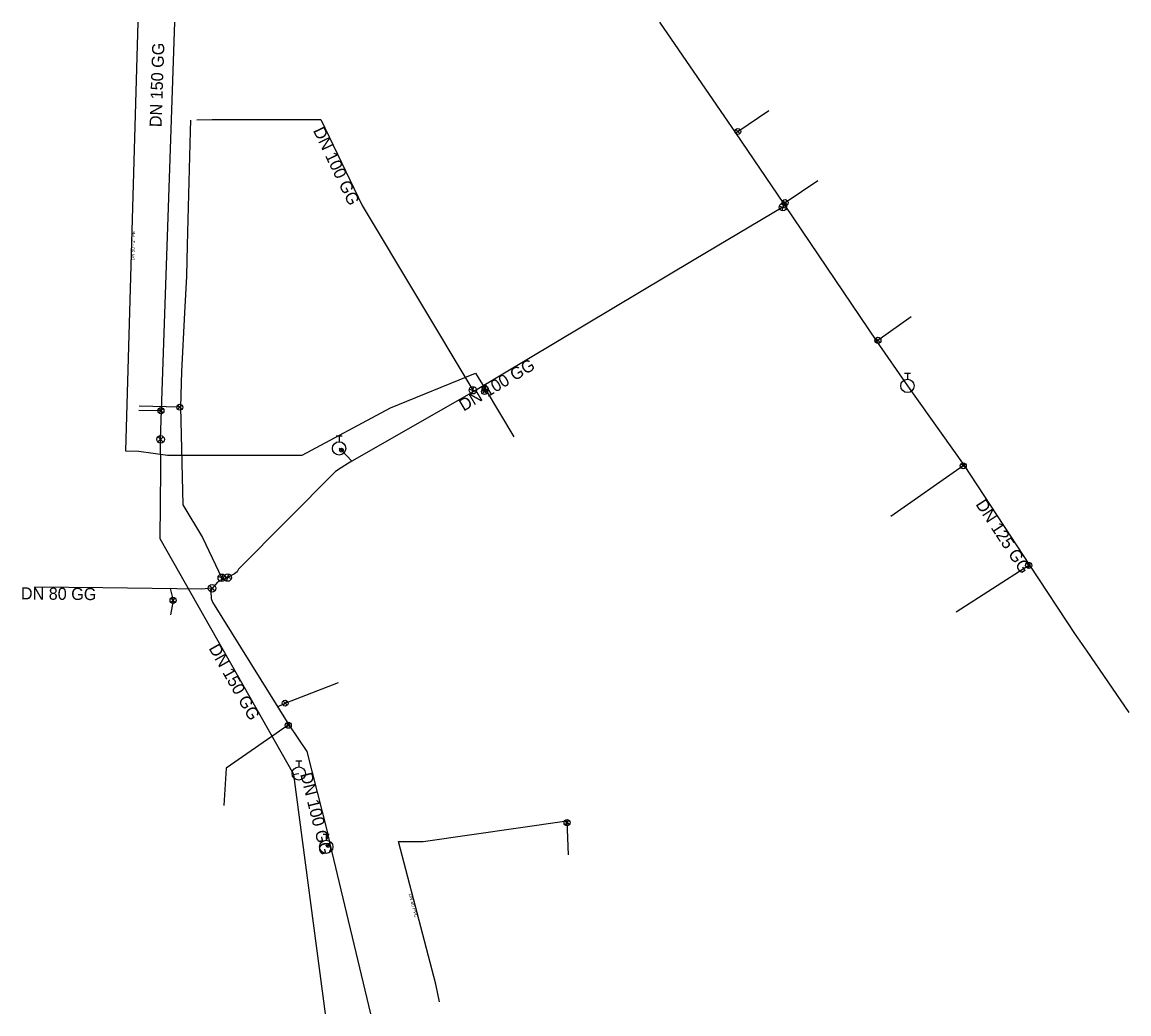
# Model space of a CAD drawing. Extents: x -464788 to -464641, y -1094693 to -1094561.
import ezdxf

# ---------------------------------------------------------------- set-up
doc = ezdxf.new("R2010")
doc.units = 0
for name, color, linetype in [('_hydrantova_odbocka_', 7, 'Continuous'), ('_pripojka_prevzato_z_dokumentace_', 7, 'Continuous'), ('_pripojka_priblizne_', 7, 'Continuous'), ('_voda_smvak_prevzato_z_dokumentace_', 7, 'Continuous'), ('_voda_smvak_priblizne_', 7, 'Continuous'), ('Default', 7, 'Continuous'), ('MoLevel 2', 7, 'Continuous'), ('MoLevel 27', 7, 'Continuous'), ('MoLevel 28', 7, 'Continuous'), ('MoLevel 32', 7, 'Continuous'), ('MoLevel 46', 7, 'Continuous'), ('MoLevel 53', 7, 'Continuous'), ('MoLevel 55', 7, 'Continuous')]:
    doc.layers.add(name, color=color, linetype=linetype)

# ---------------------------------------------------------------- blocks, each defined once
blk = doc.blocks.new('_uzaver_')
at = {"layer": 'Default'}
for p, q in [((-0.000035, -0.000035), (0.000035, 0.000035)), ((0.000035, -0.000035), (-0.000035, 0.000035))]:
    blk.add_line(p, q, dxfattribs=at)
for radius in [0.00005, 0.0000025]:
    blk.add_circle((0, 0), radius, dxfattribs=at)
blk = doc.blocks.new('_uzaver_pripojka_')
at = {"layer": 'Default'}
for p, q in [((-0.000035, -0.000035), (0.000035, 0.000035)), ((0.000035, -0.000035), (-0.000035, 0.000035))]:
    blk.add_line(p, q, dxfattribs=at)
for radius in [0.00005, 0.0000025]:
    blk.add_circle((0, 0), radius, dxfattribs=at)
blk = doc.blocks.new('_hydrant_voda_')
at = {"layer": 'Default'}
for p, q in [((-0.0000225, 0.000095), (0.0000225, 0.000095)), ((0, 0.000095), (0, 0.00005))]:
    blk.add_line(p, q, dxfattribs=at)
blk.add_circle((0, 0), 0.00005, dxfattribs=at)

msp = doc.modelspace()

# ---------------------------------------------------------------- linework, layer by layer
at = {"layer": '_hydrantova_odbocka_'}
for points in [[(-464743.89, -1094619.23), (-464745.27, -1094617.77), (-464745.58, -1094617.54)], [(-464751.57, -1094660.85), (-464751.25, -1094660.77), (-464750.94, -1094660.71)], [(-464746.83, -1094670.06), (-464747.04, -1094670.25), (-464747.29, -1094670.45)]]:
    msp.add_lwpolyline(points, dxfattribs=at)
at = {"layer": '_pripojka_prevzato_z_dokumentace_'}
msp.add_lwpolyline([(-464772.31, -1094560.93), (-464773.95, -1094617.84), (-464772.16, -1094617.92), (-464768.34, -1094618.45), (-464750.46, -1094618.43), (-464738.77, -1094612.15), (-464727.46, -1094607.57), (-464726.19, -1094609.64), (-464722.38, -1094616.02)], dxfattribs=at)
at = {"layer": '_pripojka_priblizne_'}
msp.add_line((-464726.69, -1094609.38), (-464726.28, -1094609.99), dxfattribs=at)
for points in [[(-464692.99, -1094575.63), (-464692.66, -1094575.46), (-464688.53, -1094572.65)], [(-464686.61, -1094585), (-464686.39, -1094584.89), (-464682.03, -1094581.98)], [(-464674.24, -1094603.3), (-464674.07, -1094603.18), (-464669.67, -1094600.01)], [(-464769.14, -1094612.56), (-464769.22, -1094612.53), (-464772.15, -1094612.49)], [(-464766.64, -1094612.05), (-464766.72, -1094612.07), (-464772.13, -1094611.94)], [(-464662.62, -1094619.81), (-464662.74, -1094619.86), (-464672.36, -1094626.58)], [(-464653.97, -1094633.03), (-464654.06, -1094633.08), (-464663.67, -1094639.28)], [(-464768.01, -1094636.16), (-464767.62, -1094637.72), (-464767.96, -1094639.65)], [(-464753.76, -1094651.85), (-464752.74, -1094651.37), (-464745.68, -1094648.61)], [(-464752.26, -1094654.26), (-464752.32, -1094654.31), (-464760.58, -1094660.02), (-464760.88, -1094664.97)], [(-464732.27, -1094691.01), (-464732.76, -1094688.69), (-464737.68, -1094669.72), (-464734.43, -1094669.72), (-464715.34, -1094667), (-464715.18, -1094671.52)]]:
    msp.add_lwpolyline(points, dxfattribs=at)
at = {"layer": '_voda_smvak_prevzato_z_dokumentace_'}
for p, q in [((-464703.07, -1094560.93), (-464692.99, -1094575.63)), ((-464686.68, -1094585.5), (-464698.44, -1094592.52)), ((-464686.4, -1094585.3), (-464686.68, -1094585.5)), ((-464698.44, -1094592.52), (-464727.72, -1094609.99)), ((-464727.72, -1094609.99), (-464743.9, -1094619.23)), ((-464761.14, -1094634.75), (-464761.06, -1094635.01)), ((-464762.37, -1094636.1), (-464762.44, -1094636.11)), ((-464747.38, -1094692.63), (-464751.57, -1094660.85)), ((-464746.83, -1094670.06), (-464741.41, -1094692.63))]:
    msp.add_line(p, q, dxfattribs=at)
for points in [[(-464769.27, -1094616.34), (-464768.28, -1094586.85), (-464767.38, -1094560.93)], [(-464765.3, -1094573.93), (-464765.36, -1094575.41), (-464765.75, -1094590.54), (-464765.85, -1094594.66), (-464766.09, -1094599.53), (-464766.49, -1094607.33), (-464766.64, -1094612.05), (-464766.34, -1094625.05), (-464763.72, -1094629.36), (-464761.14, -1094634.75)], [(-464692.99, -1094575.63), (-464686.61, -1094585), (-464686.4, -1094585.3)], [(-464686.4, -1094585.3), (-464674.24, -1094603.3), (-464670.15, -1094609.24)], [(-464670.15, -1094609.24), (-464662.62, -1094619.81), (-464653.97, -1094633.03), (-464647.91, -1094642.23), (-464646.34, -1094644.46), (-464640.76, -1094652.63)], [(-464751.57, -1094660.85), (-464769.32, -1094629.55), (-464769.23, -1094620.31), (-464769.27, -1094616.34)], [(-464743.9, -1094619.23), (-464744.33, -1094619.48), (-464745.31, -1094620.13), (-464746.07, -1094620.59), (-464758.95, -1094633.56), (-464759.11, -1094633.95), (-464759.46, -1094634.18), (-464760.37, -1094634.69)], [(-464761.06, -1094635.01), (-464761.74, -1094635.29), (-464762.3, -1094635.97), (-464762.37, -1094636.1)], [(-464760.37, -1094634.69), (-464760.89, -1094634.93), (-464761.06, -1094635.01)], [(-464762.44, -1094636.11), (-464763.84, -1094636.22), (-464776.92, -1094636.05), (-464786.01, -1094635.96)], [(-464762.37, -1094636.1), (-464762.59, -1094636.52), (-464762.57, -1094637.46), (-464762.39, -1094637.96), (-464752.26, -1094654.26), (-464749.85, -1094657.8), (-464747.18, -1094668.41), (-464746.83, -1094670.06)]]:
    msp.add_lwpolyline(points, dxfattribs=at)
at = {"layer": '_voda_smvak_priblizne_'}
msp.add_line((-464727.82, -1094609.82), (-464727.72, -1094609.99), dxfattribs=at)
msp.add_lwpolyline([(-464764.44, -1094573.92), (-464762.43, -1094573.88), (-464759.23, -1094573.88), (-464748, -1094573.85), (-464742.53, -1094585.28), (-464727.82, -1094609.82)], dxfattribs=at)

# ---------------------------------------------------------------- block references
at = {"layer": 'MoLevel 27'}
for p, xscale, yscale, rotation in [((-464686.68, -1094585.5), 10000.000000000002, 9999.999999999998, -149.1256317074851), ((-464727.83, -1094609.81), 10000, 10000.000000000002, -59.67876301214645), ((-464769.27, -1094616.34), 10000.000000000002, 10000, 88.4308199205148), ((-464745.27, -1094617.77), 5000, 5000, 142.236922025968), ((-464761.15, -1094634.72), 10000, 9999.999999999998, 115.71448229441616), ((-464760.37, -1094634.69), 10000.000000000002, 10000.000000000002, 28.023028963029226), ((-464747.04, -1094670.25), 5000, 4999.999999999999, -140.10216525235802)]:
    msp.add_blockref('_uzaver_', p, dxfattribs=dict(at, xscale=xscale, yscale=yscale, rotation=rotation))
at = {"layer": 'MoLevel 27', "xscale": 10000, "yscale": 10000}
msp.add_blockref('_uzaver_', (-464762.44, -1094636.11), dxfattribs=at)
at = {"layer": 'MoLevel 28', "xscale": 17636.68430335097, "yscale": 17636.68430335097}
for p in [(-464670.15, -1094609.24), (-464745.58, -1094617.54), (-464750.94, -1094660.71), (-464747.29, -1094670.45)]:
    msp.add_blockref('_hydrant_voda_', p, dxfattribs=at)
at = {"layer": 'MoLevel 53', "xscale": 7999.999999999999, "yscale": 7999.999999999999}
for p in [(-464692.66, -1094575.46), (-464686.39, -1094584.89), (-464674.07, -1094603.18), (-464726.28, -1094609.99), (-464769.22, -1094612.53), (-464766.72, -1094612.07), (-464662.74, -1094619.86), (-464654.06, -1094633.08), (-464767.62, -1094637.72), (-464752.74, -1094651.37), (-464752.32, -1094654.31)]:
    msp.add_blockref('_uzaver_pripojka_', p, dxfattribs=at)
at = {"layer": 'MoLevel 53', "yscale": 7999.999999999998}
for p, xscale, rotation in [((-464726.19, -1094609.64), 7999.999999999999, -59.17182479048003), ((-464715.33, -1094667.24), 8000, 9.02978119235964)]:
    msp.add_blockref('_uzaver_pripojka_', p, dxfattribs=dict(at, xscale=xscale, rotation=rotation))

# ---------------------------------------------------------------- texts
at = {"layer": 'MoLevel 2'}
msp.add_text('DN 100 GG', height=1.605, rotation=295.5673, dxfattribs=at).set_placement((-464749.07, -1094575.32))
at = {"layer": 'MoLevel 32'}
msp.add_text('DN 80 PVC', height=0.455, rotation=284.5478, dxfattribs=at).set_placement((-464736.35, -1094676.71))
at = {"layer": 'MoLevel 46'}
for s, rotation, p in [('DN 150 GG', 88.016, (-464769.15, -1094574.9)), ('DN 100 GG', 30.8244, (-464729.05, -1094612.66)), ('DN 125 GG', 303.2082, (-464661.16, -1094624.96)), ('DN 80 GG', 359.4299, (-464787.82, -1094637.59)), ('DN 150 GG', 299.559, (-464762.93, -1094644.07)), ('DN 100 GG', 284.1472, (-464750.75, -1094660.8))]:
    msp.add_text(s, height=1.605, rotation=rotation, dxfattribs=at).set_placement(p)
at = {"layer": 'MoLevel 55'}
msp.add_text("DN 50 - 2'' PE", height=0.455, rotation=88.349, dxfattribs=at).set_placement((-464772.76, -1094592.59))

doc.saveas('drawing.dxf')
